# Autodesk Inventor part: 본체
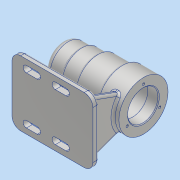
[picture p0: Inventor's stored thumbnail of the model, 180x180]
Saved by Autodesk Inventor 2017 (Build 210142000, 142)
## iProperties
Part Number: 본체
Material: 알루미늄 6061
Document SubType Name: Modeling
Designer: MRC
Density: 2.7 g/cm^3
Appearance: 알루미늄 - 평지
Mass: 688.719 g
Surface Area: 705.682 cm^2
Volume: 255.081 cm^3
Author: MRC
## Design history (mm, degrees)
sketch "스케치2"
  geometry: L1 (56, 0)-(56, 34); L2 (56, 34)-(24, 34); L3 (24, 34)-(24, 30); L4 (24, 30)-(-10, 30); L5 (-10, 30)-(-10, 27); L6 (-10, 27)-(-32, 27); L7 (-32, 27)-(-32, 25); L8 (-32, 25)-(-56, 25); L9 (-56, 25)-(-56, 0); L10 (-56, 0)-(56, 0); 2 further points
  constraints: 20 end point, 8 perpendicular, 2 midpoint, 1 coincident, 1 horizontal, 1 vertical
  dimensions: "d0" = 68 diameter of L2 L10; "d1" = 60 diameter of L4 L10; "d2" = 54 diameter of L6 L10; "d3" = 50 diameter of L8 L10; "d4" = 24 distance of L7.end L8.end; "d5" = 46 distance from line of L5.end L9; "d6" = 80 distance from line of L3.end L9; "d7" = 112 distance between parallel lines of L1 L9
revolve "회전1" sketch "스케치2" stored, may be unused: angle "d8" = 90 deg
sketch "스케치3"
  geometry: L1 (56, -34)-(56, 34) reference; L2 (56, 21)-(41, 21); L3 (41, 21)-(41, 24); L4 (41, 24)-(-13, 24); L5 (-13, 24)-(-13, 21); L6 (-13, 21)-(-25, 21); L7 (-25, 21)-(-25, 17.5); L8 (-25, 17.5)-(-43, 17.5); L9 (-43, 17.5)-(-43, 16); L10 (-43, 16)-(-47, 16); L11 (-47, 16)-(-47, 10.5); L12 (-47, 10.5)-(-50, 10.5); L13 (-50, 10.5)-(-50, 0); L14 (-50, 0)-(56, 0); 1 further point
  constraints: 26 end point, 11 perpendicular, 1 horizontal, 1 midpoint, 1 point on line
  dimensions: "d9" = 21 diameter of L12 L14; "d10" = 15 distance of L2.start L2.end; "d11" = 54 distance of L3.end L4.end; "d12" = 12 distance of L5.end L6.end; "d13" = 18 distance of L7.end L8.end; "d14" = 3 distance of L11.end L12.end; "d15" = 4 distance of L9.end L10.end; "d16" = 42 diameter of L2 L14; "d17" = 48 diameter of L4 L14; "d18" = 32 diameter of L10 L14; "d19" = 35 diameter of L8 L14; "d20" = 42 diameter of L6 L14
revolve "회전2" sketch "스케치3" stored, may be unused: angle "d21" = 90 deg
fillet "모깎기1" dims "d22" = 3, "d23" = 0.3
chamfer "모따기1" distance "d24" = 1; stored, may be unused: second distance "d25" = 2, angle "d26" = 45 deg
sketch "스케치5"
  geometry: L1 (-56, -62)-(56, -62); L2 (56, -62)-(56, -70); L3 (56, -70)-(-56, -70); L4 (-56, -70)-(-56, -62); 2 further points
  constraints: 8 end point, 2 parallel, 1 horizontal, 1 midpoint, 1 perpendicular, 1 vertical alignment
  dimensions: "d27" = 8 distance of L1.end L2.end; "d28" = 70 distance from line of L3 point (0, 0); "d29" = 112 distance of L2.end L3.end
extrude "돌출1" join sketch "스케치5" stored distance "d30" = 90; taper "d31" = 0 deg
sketch "스케치6"
  geometry: L1 (0, 90)-(0, 0) reference; L2 (0, 90)-(112, 90) reference; L3 (20, 78)-(35, 78); L4 (20, 82.5)-(35, 82.5); L5 (35, 73.5)-(20, 73.5); L6 (60, 78)-(75, 78); L7 (60, 73.5)-(75, 73.5); L8 (75, 82.5)-(60, 82.5); A1 r 4.5 centre (20, 78) between (20, 82.5) and (20, 73.5); A2 r 4.5 centre (35, 78) between (35, 73.5) and (35, 82.5); A3 r 4.5 centre (60, 78) between (60, 82.5) and (60, 73.5); A4 r 4.5 centre (75, 78) between (75, 73.5) and (75, 82.5); 3 further points
  constraints: 16 end point, 8 point on circle, 8 tangent, 4 centre point, 3 parallel, 2 midpoint, 2 point on line
  dimensions: "d32" = 15 distance of L4.start L4.end; "d33" = 15 distance of L8.start L8.end; "d34" = 20 distance from line of L3.start L1; "d35" = 25 distance of L6.start L3.end; "d36" = 4.5 radius of A2; "d37" = 4.5 radius of A4; "d38" = 33 vertical distance of point (27.5, 78) point (56, 45)
extrude "돌출2" cut sketch "스케치6" stored distance "d39" = 90; taper "d40" = 0 deg
fillet "모깎기2" dims "d41" = 12
fillet "모깎기3" dims "d42" = 3, "d43" = 8
sketch "스케치7"
  geometry: L1 (-34, 0)-(0, 0); L2 (13, 22.517)-(0, 0); C1 r 22 at (0, 0) reference; 1 further point
  constraints: 4 end point, 1 horizontal, 1 horizontal alignment, 1 other
  dimensions: "d45" = 120 deg angle of L1 L2; "d46" = 26 distance of point (0, 0) L2.start
hole "구멍1" sketch "스케치7" at (13, 22.517) diameter "d47" = 3.242; stored, may be unused: countersink angle "d51" = 90 deg, drill point angle "d53" = 118 deg; dims "d48" = 8, "d49" = 4, "d50" = 2, "d52" = 11
node "작업 평면1"
sketch "스케치8"
  geometry: L1 (37, -62)-(23.409, -24.658); L2 (33, -62)-(42, -62) reference; L3 (45, -70)-(45, -65) reference; L4 (-37.5, -62)-(-28.5, -62) reference; L5 (-37.5, -62)-(-28.5, -62) reference; L6 (-37, -62)-(-23.409, -24.658); L7 (-45, -65)-(-45, -70) reference; L8 (28.5, -62)-(37.5, -62) reference; L9 (-37, -62)-(37, -62); A1 r 34 centre (0, 0) between (-23.409, -24.658) and (23.409, -24.658) reference; 1 further point
  constraints: 6 end point, 2 point on circle, 2 point on line, 1 collinear
  dimensions: "d58" = 110 deg angle of L1 L2; "d59" = 8 distance from line of L1.start L3; "d61" = 8 distance from line of L7 L6.start; "d62" = 110 deg angle of L6 L4
extrude "돌출3" join sketch "스케치8" distance "d63" = 8; taper "d64" = 0 deg
sketch "스케치9"
  geometry: L1 (-24.293, -44.434)-(-29, -62); L2 (-21, -62)-(-36, -62) reference; L3 (48, -62)-(48, -24.658) reference; 1 further point
  constraints: 2 end point, 1 point on line
  dimensions: "d65" = 105 deg angle of L1 L2; "d66" = 77 distance from line of L1.end L3
feature "리브1" sketch "스케치9" dims "d67" = 8, "d68" = 8, "d69" = 0, "d70" = 0, "d71" = 1, "d72" = 1
fillet "모깎기4" dims "d73" = 3
fillet "모깎기5" dims "d74" = 3
fillet "모깎기6" dims "d75" = 3
sketch "스케치10"
  geometry: L1 (-12, -9)-(-12, -75) reference; 2 further points
  constraints: 1 horizontal alignment, 1 other
  dimensions: "d76" = 12 distance from line of L1 point (0, -42)
feature "엠보싱1" sketch "스케치10" dims "d0" = 68, "d1" = 60, "d2" = 54, "d3" = 50, "d4" = 24, "d5" = 46, "d6" = 80, "d7" = 112, "d9" = 21, "d10" = 15, "d11" = 54, "d12" = 12, "d13" = 18, "d14" = 3, "d15" = 4, "d16" = 42, "d17" = 48, "d18" = 32, "d19" = 35, "d20" = 42, "d77" = 0.5, "d78" = 0
node "솔리드1"
mirror "미러1"
pattern_circular "원형 패턴1" dims angle "d55" = 360 deg
other parameters: "d57" = -8
